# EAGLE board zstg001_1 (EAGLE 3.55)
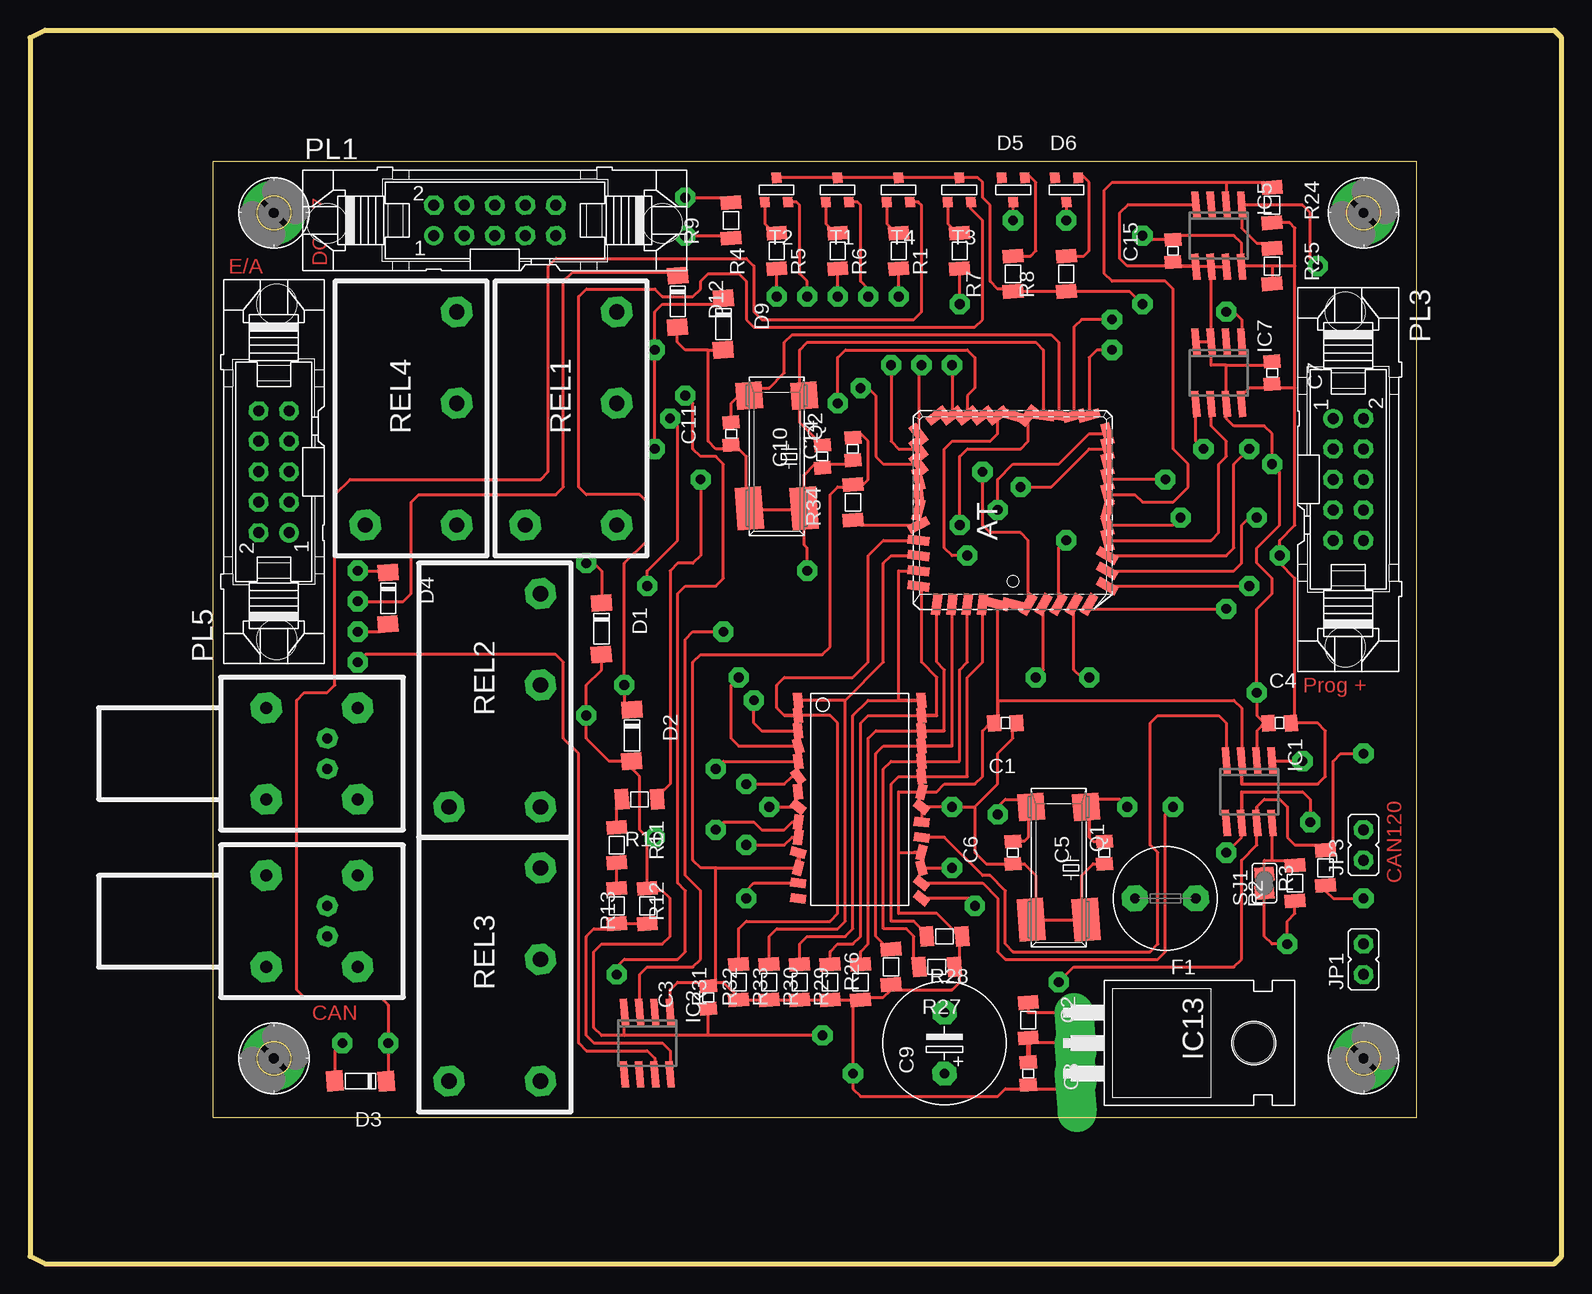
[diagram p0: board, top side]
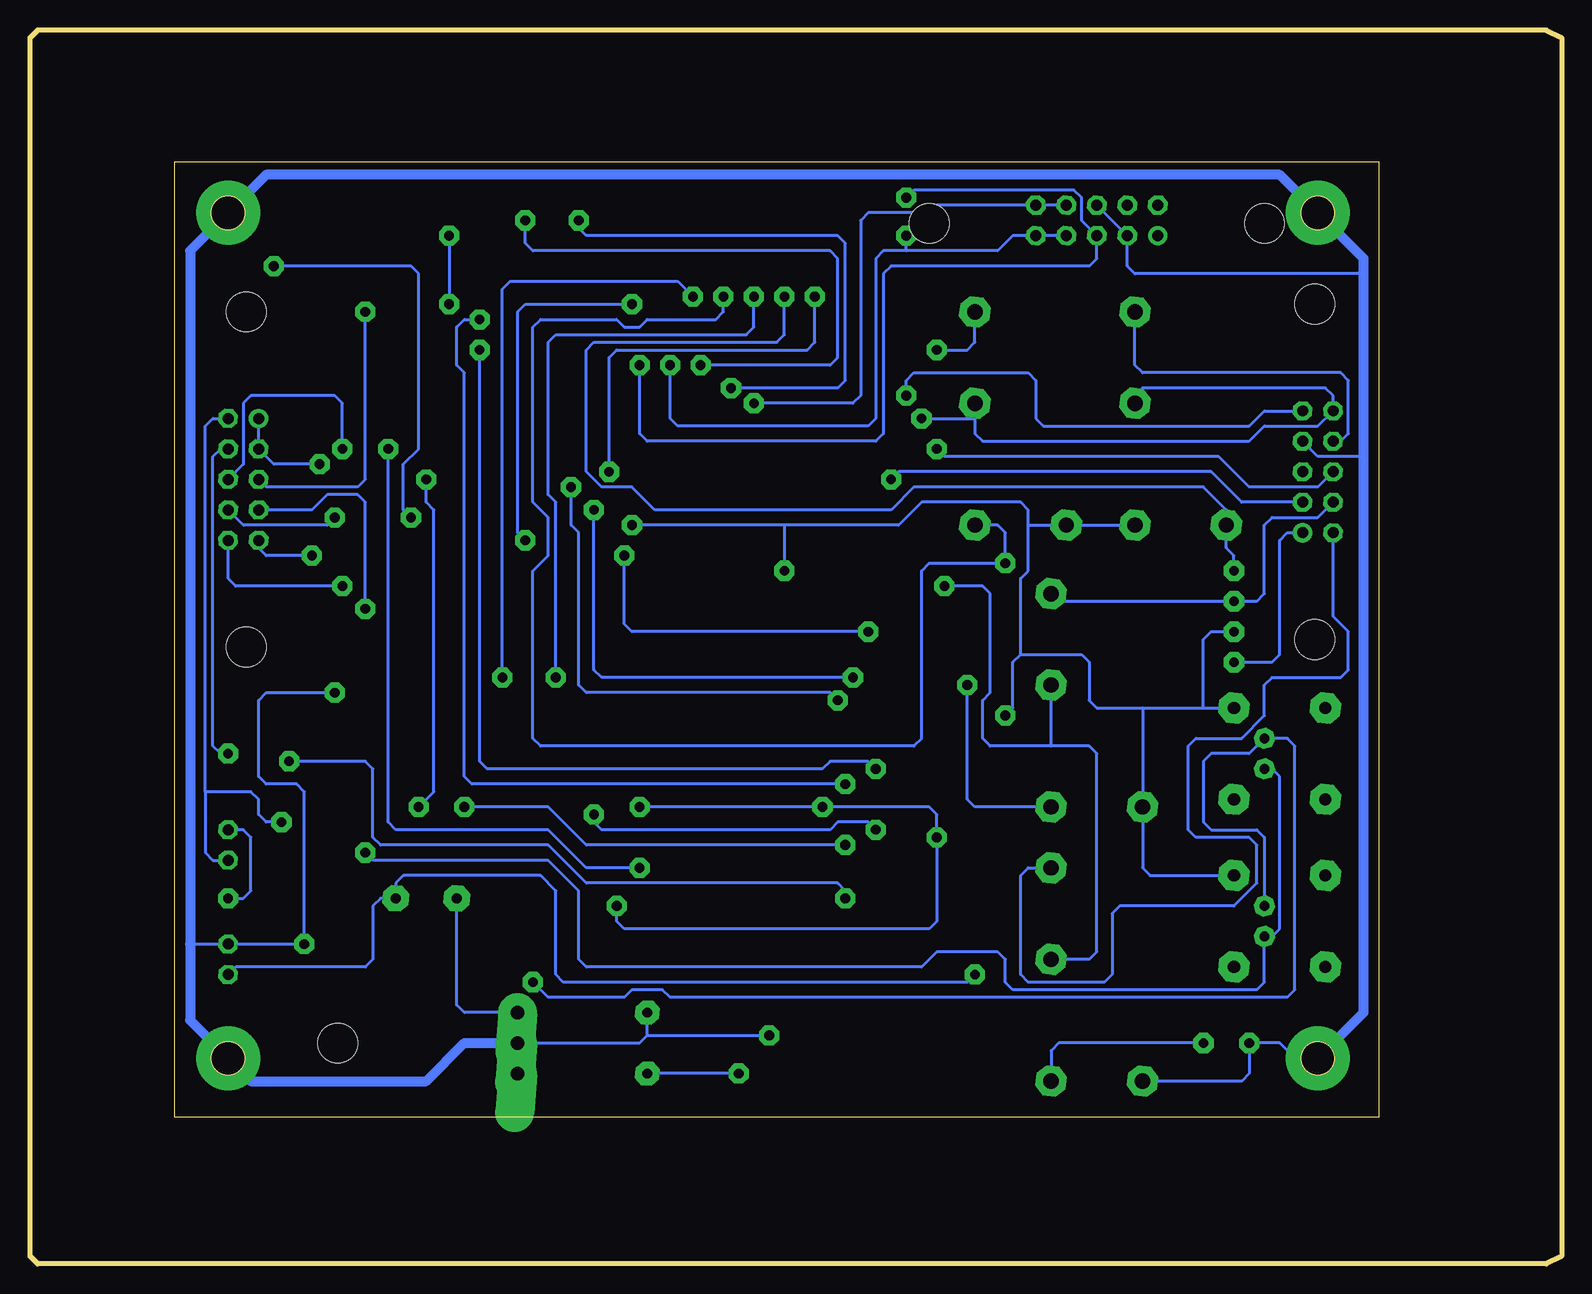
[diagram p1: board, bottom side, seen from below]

Size 127.64 x 102.87 mm. Coordinates in mm from the lower left corner, seen from the top.
Outline: 115.56,12.23 115.56,91.91 15.24,91.91 15.24,12.23 115.56,12.23
Outline: 0,0.63 1.27,0 127,0 127.64,0.63 127.64,102.23 127,102.87 1.27,102.87 0,102.23 0,0.63
Copper layers used: Top, Bottom
vRestrict: area 69.9,50.8 to 94,74.9

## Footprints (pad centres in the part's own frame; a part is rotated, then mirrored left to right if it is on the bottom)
05 = smd 1.092 x 1.397 rotated 4.4:  0.94,0 | smd 1.092 x 1.397 rotated 4.3:  -0.94,0
06 = smd 1.143 x 1.702 rotated 4.4:  1.473,0 | smd 1.143 x 1.702 rotated 4.3:  -1.473,0
-5 = drill 0.813 pad 2.007 octagon:  -2.54,0;  2.54,0
D-80 = smd 1.397 x 1.702 rotated 4.4:  -2.388,0 | smd 1.397 x 1.702 rotated 4.3:  1.905,-0.025
T-23 = smd 0.787 x 0.889 rotated 4.4:  0.991,1.016 | smd 0.787 x 0.889 rotated 4.3:  -0.94,1.016 | smd 0.787 x 0.889 rotated 4.5:  0.025,-1.016
5 = drill 0.813 pad 2.159 octagon:  -2.54,0;  2.54,0
8 = smd 0.6 x 2.2 rotated 4.4:  -0.635,-2.6 | smd 0.6 x 2.2 rotated 4.8:  -0.635,2.6 | smd 0.6 x 2.2 rotated 4.3:  -1.905,-2.6 | smd 0.6 x 2.2 rotated 4.5:  0.635,-2.6 | smd 0.6 x 2.2 rotated 4.6:  1.905,-2.6 | smd 0.6 x 2.2 rotated 4.9:  -1.905,2.6 | smd 0.6 x 2.2 rotated 4.7:  0.635,2.6;  1.905,2.6
CC-44 = smd 0.76 x 1.8 rotated 74.5: 0 -1.27,-7.86; 1 1.27,-7.86; 2 2.54,-7.86; 3 3.81,-7.86; 4 5.08,-7.86; 5 6.35,-7.86; N 2.54,7.86 | smd 1.8 x 0.76 rotated 29.5: 0 -7.86,-1.27; 1 -7.86,-2.54; 2 -7.86,-3.81; 3 -7.86,-5.08; 4 -7.86,-6.35 | smd 1.8 x 0.76 rotated 7: 0 -7.86,2.54; 1 -7.86,3.81; 2 -7.86,5.08; 3 -7.86,6.35 | smd 1.8 x 0.76 rotated 52: 0 7.86,1.27; 1 7.86,2.54; 2 7.86,3.81; 3 7.86,5.08; 4 7.86,6.35 | smd 0.76 x 1.8 rotated 7: 4 -6.35,7.86; 5 -5.08,7.86; 6 -3.81,7.86; 7 -2.54,7.86 | smd 0.76 x 1.8 rotated 52: 5 6.35,7.86; 6 5.08,7.86; 7 3.81,7.86 | smd 0.76 x 1.8 rotated 29.5: 5 -6.35,-7.86; 6 -5.08,-7.86; 7 -3.81,-7.86 | smd 1.8 x 0.76 rotated 74.5: 6 7.86,-6.35; 7 7.86,-5.08 | smd 0.76 x 1.8 rotated 275.7: /PR 1.27,7.86 | smd 1.8 x 0.76 rotated 97.7: L1 7.86,-2.54; L2 7.86,-3.81 | smd 0.76 x 1.8 rotated 28.6: VPP -1.27,7.86 | smd 0.76 x 1.8 rotated 74.7:  -2.54,-7.86 | smd 0.76 x 1.8 rotated 74.4:  0,-7.86;  0,7.86 | smd 1.8 x 0.76 rotated 74.4:  -7.86,0;  7.86,0 | smd 1.8 x 0.76 rotated 75.1:  -7.86,1.27 | smd 1.8 x 0.76 rotated 321.2:  7.86,-1.27
-28L = smd 0.762 x 1.27 rotated 321.2: 1 1.27,-5.207; 2 1.27,5.08; 3 8.89,5.08 | smd 0.762 x 1.27 rotated 75.1: 1 0,5.08; 2 5.08,5.08; 3 6.35,-5.207 | smd 0.762 x 1.27 rotated 74.7: / 6.35,5.08 | smd 0.762 x 1.27 rotated 321.4: / 7.62,5.08 | smd 0.762 x 1.27 rotated 275.7: /AS -5.08,-5.207 | smd 0.762 x 1.27 rotated 97.2: E -2.54,-5.207 | smd 0.762 x 1.27 rotated 344.3: E 5.08,-5.207 | smd 0.762 x 1.27 rotated 97.7: L1 2.54,-5.207; L2 3.81,-5.207 | smd 0.762 x 1.27 rotated 275.9: OUT 0,-5.207 | smd 0.762 x 1.27 rotated 95.7:  -7.62,-5.207;  -6.35,-5.207;  -1.27,5.08;  -2.54,5.08;  -3.81,5.08;  -5.08,5.08;  -6.35,5.08;  -7.62,5.08 | smd 0.762 x 1.27 rotated 73.4:  -3.81,-5.207 | smd 0.762 x 1.27 rotated 52.6:  -1.27,-5.207 | smd 0.762 x 1.27 rotated 187.2:  2.54,5.08;  3.81,5.08 | smd 0.762 x 1.27 rotated 187.4:  8.89,-5.207;  7.62,-5.207
220H = drill 1.118 pad 3.251 offset:  -2.54,-10.16;  0,-10.16;  2.54,-10.16 | hole 3.302: 0,4.826
1 = drill 0.914 pad 1.6 octagon:  0,-1.27;  0,1.27
2,8-P = drill 2.794 pad 5.334 round: 8 0,0
V = drill 0.914 pad 1.6 round:  -5.08,-1.27 | drill 0.914 pad 1.6 octagon:  -5.08,1.27;  -2.54,-1.27;  -2.54,1.27;  0,-1.27;  0,1.27;  2.54,-1.27;  2.54,1.27;  5.08,-1.27;  5.08,1.27 | hole 3.302: 13.97,-0.254; -13.97,-0.254
N_EPL = drill 1.016 pad 2.54 octagon: 1 -3.81,3.81; 2 3.81,3.81; 3 -3.81,-3.81; 4 3.81,-3.81 | drill 0.813 pad 1.676 octagon: H -1.27,1.27; L 1.27,1.27
SMX = smd 3.556 x 2.184 rotated 4.4:  4.318,-2.286 | smd 3.556 x 2.184 rotated 4.5:  4.318,2.286 | smd 2.286 x 2.184 rotated 4.3:  -5.08,-2.286 | smd 2.286 x 2.184 rotated 4.6:  -5.08,2.286
LAIS_R = drill 1.27 pad 2.54 octagon:  -12.7,5.08;  -12.7,-2.54;  -2.54,-2.54;  5.08,-2.54
 = smd 1.168 x 1.6 rotated 4.3:  -0.762,0 | smd 1.168 x 1.6 rotated 4.4:  0.762,0

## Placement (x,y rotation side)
C1  100n  [05]  81.28,45.08 180 top
C2  330n  [06]  83.19,20.32 270 top
C3  100n  [05]  56.52,22.23 90 top
C4  100n  [05]  104.14,45.08 0 top
C5  15pF  [05]  89.53,34.29 90 top
C6  15pF  [05]  81.92,34.29 90 top
C7  100n  [05]  103.5,74.3 270 top
C8  100n  [05]  83.19,15.88 270 top
C9  Elko 470uF  [-5]  76.2,18.41 90 top
C10  30pF +-10pF  [05]  66.04,67.31 90 top
C11  30 pF+-10pF  [05]  58.42,69.22 90 top
C14  100n  [05]  68.58,67.94 90 top
C15  100n  [05]  95.25,84.45 90 top
D1  SMD4148  [D-80]  47.62,52.7 270 top
D2  SMD4148  [D-80]  50.16,43.81 270 top
D3  SMD4148  [D-80]  27.3,15.24 180 top
D4  SMD4148  [D-80]  29.84,55.25 270 top
D5  grn  [T-23]  81.92,89.53 0 top
D6  rot  [T-23]  86.36,89.53 0 top
D9  SMD4148  [D-80]  57.78,78.11 270 top
D12  SMD4148  [D-80]  53.98,80.01 270 top
F1  T200mA  [5]  94.61,30.48 180 top
IC1  PCA82C250  [8]  101.6,39.37 180 top
IC2  DS2450  [8]  51.44,18.41 180 top
IC3  AT89S53  [CC-44]  81.92,62.86 90 top
IC4  SJA1000  [-28L]  69.22,39.37 270 top
IC5  DS1621  [8]  99.06,85.73 180 top
IC7  MAX700  [8]  99.06,74.3 180 top
IC13  78S05  [220H]  97.16,18.41 270 top
JP1  2-polig  [1]  111.12,25.4 0 top
JP3  CAN-Abschluá  [1]  111.12,34.92 0 top
PAD1  BO2,8P  [2,8-P]  20.32,87.63 0 top
PAD2  BO2,8P  [2,8-P]  20.32,17.14 0 top
PAD3  BO2,8P  [2,8-P]  111.12,17.14 0 top
PAD4  BO2,8P  [2,8-P]  111.12,87.63 0 top
PL1  06V  [V]  38.73,87 0 top
PL2  CAN_BUS  [N_EPL]  23.5,28.57 270 top
PL3  10V  [V]  109.86,65.41 270 top
PL4  CAN_BUS  [N_EPL]  23.5,42.55 270 top
PL5  10V  [V]  20.32,66.04 90 top
Q1  16MHZ  [SMX]  85.72,33.02 270 top
Q2  16MHZ  [SMX]  62.23,67.31 270 top
R1  4k7  [06]  77.47,84.45 90 top
R2  47k  [06]  105.41,31.75 90 top
R3  120R  [06]  107.95,33.02 90 top
R4  4k7  [06]  62.23,84.45 90 top
R5  4k7  [06]  67.31,84.45 90 top
R6  4k7  [06]  72.39,84.45 90 top
R7  2k7  [06]  81.92,82.55 90 top
R8  2k7  [06]  86.36,82.55 90 top
R9  10k  [06]  58.42,87 90 top
R10  10k  [06]  50.8,38.73 180 top
R11  10k  [06]  48.9,34.92 270 top
R12  10k  [06]  48.9,29.84 270 top
R13  10k  [06]  51.44,29.84 90 top
R24  1k  [06]  103.5,88.27 270 top
R25  1k  [06]  103.5,83.19 270 top
R26  4k7  [06]  71.75,24.77 90 top
R27  4k7  [06]  75.56,24.77 180 top
R28  4k7  [06]  76.2,27.3 180 top
R29  4k7  [06]  69.22,23.49 90 top
R30  4k7  [06]  66.67,23.49 90 top
R31  4k7  [06]  59.05,23.49 90 top
R32  4k7  [06]  61.59,23.49 90 top
R33  4k7  [06]  64.13,23.49 90 top
R34  4k7  [06]  68.58,63.5 90 top
REL1  REL_RE  [LAIS_R]  46.36,74.3 90 top
REL2  REL_RE  [LAIS_R]  40,50.8 90 top
REL3  REL_RE  [LAIS_R]  40,27.94 90 top
REL4  REL_RE  [LAIS_R]  33.02,74.3 90 top
SJ1  SJ  []  102.87,31.75 90 top
T1  BC818  [T-23]  67.31,89.53 180 top
T2  BC818  [T-23]  62.23,89.53 180 top
T3  BC818  [T-23]  77.47,89.53 180 top
T4  BC818  [T-23]  72.39,89.53 180 top

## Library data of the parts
C1-C8 C10 C11 C14 C15 D1-D6 D9 D12 R1-R13 R24-R34 T1-T4 = smd
C9 = discrete
F1 = fuse
IC1-IC5 IC7 PL2 PL4 REL1-REL4 = andit4at
IC13 = linear
JP1 JP3 = jumps
PAD1-PAD4 = holes
PL1 PL3 PL5 = pinh-v
Q1 Q2 = quartz
SJ1 = jumper

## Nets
+5V: C1. C3. C4. C7. C8. C9. C14. C15. IC1. IC2. IC3. IC4.1 IC4.2 IC4.3 IC4.E IC5. IC7. IC13. PL3. R7. R8. R24. R25. R26. R27. R28. R29. R30. R31. R32. R33. R34. T1. T2. T3. T4.
GND: C1. C2. C3. C4. C5. C6. C7. C8. C9. C10. C11. C14. C15. D1. D2. D3. D4. D9. D12. IC1. IC2. IC3. IC4. IC4.1 IC4.2 IC4.3 IC5. IC7. IC13. JP1. PAD1.8 PAD2.8 PAD3.8 PAD4.8 PL1. PL2.1 PL3. PL4.1 PL5. Q1. Q2. R2. R13. REL1. REL2. REL3. REL4. SJ1.
N$1: IC3.0 IC4. R28.
N$2: IC3.1 IC4. R27.
N$3: IC3.5 IC4. R33.
N$4: IC3.VPP R34.
N$5: IC3.7 IC4. R31.
N$6: IC3.3 R6.
N$7: IC3.2 R1.
N$9: IC1. IC4.
N$10: IC3.1 R5.
N$11: C11. IC3.L2 Q2.
N$13: IC3.0 R4.
N$15: R4. T2.
N$16: IC1. PL2.H PL3. PL4.H R3.
N$17: D3. REL3. T4.
N$18: R5. T1.
N$19: D2. REL2. T3.
N$20: R1. T3.
N$21: R6. T4.
N$22: D1. REL1. T1.
N$23: D6. R8.
N$24: D4. REL4. T2.
N$25: D6. IC3.6
N$26: D5. IC3.7
N$28: IC3.5 PL1. R9.
N$29: PL5. REL1. REL2. REL3. REL4.
N$30: PL5. R10.
N$31: IC3.3 PL1. R9.
N$32: IC3.2 PL1.
N$33: D12. PL5. REL2.
N$34: PL5. REL3.
N$35: D9. PL5. REL1.
N$36: IC1. JP3. PL2.L PL3. PL4.L
N$37: IC3.4 IC4./AS
N$38: IC3.6 PL3.
N$39: IC3.5 PL3.
N$40: IC3.7 PL3.
N$41: IC3. IC7.
N$42: IC3.5 IC4.
N$43: PL5. REL4.
N$44: IC3.1 IC5. R24.
N$45: IC3.0 IC5. R25.
N$46: IC3.6 IC4.E
N$47: IC3.7 IC4.
N$48: IC3.2 IC4./
N$49: IC7. PL3.
N$50: IC4./ IC7.
N$51: C5. IC4.L2 Q1.
N$52: C6. IC4.L1 Q1.
N$53: IC2. R12. R13.
N$54: IC2. IC3.0
N$55: IC1. IC4.
N$56: R10. R11.
N$59: D5. R7.
N$60: C2. F1. IC13.
N$61: F1. JP1. PL5.
N$63: IC1. R2. SJ1.
N$64: R11. R12.
N$65: JP3. R3.
N$69: IC2. PL5.
N$70: C10. IC3.L1 Q2.
N$79: IC3.4 PL3.
N$102: IC3.2 IC4. R26.
N$104: IC3.3 IC4. R29.
N$105: IC3.4 IC4. R30.
N$106: IC3.6 IC4. R32.

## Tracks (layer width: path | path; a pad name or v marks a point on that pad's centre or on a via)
+5V  (via drill 0.81 pad 1.68)
  Top 0.254: 71.96,23.49 R26. 71.75,22.86 | 73.66,34.29 74.3,34.29 72.39,34.29 | 64.13,33.15 IC4.3 | 64.13,33.15 64.13,34.29 | 72.39,34.29 72.39,39.37 IC4.1 75.56,39.37 76.2,40 78.74,40 79.38,40.64 79.38,44.45 80.01,45.08 | 72.39,34.29 72.39,29.21 75.56,29.21 77.47,27.3 R28. 77.47,27.1 77.47,24.77 | 77.47,24.77 R27. | 83.19,14.6 86.36,14.6 86.36,15.24 IC13. | IC4.E 64.01,33.15 64.13,33.02 | 100.97,40 107.31,40 107.95,40.64 107.95,44.45 107.31,45.08 105.41,45.08 | 80.64,46.99 80.64,45.08 80.34,45.08 80.01,45.08 | 80.64,46.99 80.64,55 | 103.5,83.19 100.97,83.19 | 100.97,83.19 100.97,85.09 100.33,85.73 95.25,85.73 95.25,85.39 93.04,85.39 v92.71,85.73 | 105.41,73.03 105.41,83.19 | 103.5,73.03 103.5,73.36 | 105.41,73.03 103.5,73.03 | 103.5,73.03 101.6,73.03 101.03,72.45 101.03,71.75 100.97,71.75 100.97,71.69 | 105.41,73.03 105.41,61.59 104.14,60.33 v104.14,59.05 104.14,58.42 105.41,57.15 105.41,45.08 | 104.78,45.08 105.08,45.08 105.41,45.08 | 103.5,86.79 104.98,86.79 105.41,86.36 105.41,83.19 | 105.41,83.19 103.5,83.19 | 103.5,83.19 103.5,81.71 | 81.92,81.28 R7. | 81.92,81.28 82.12,81.08 R8. 91.64,81.08 v92.71,80.01 | T2. 62.2,90.78 62.23,90.81 62.48,90.55 T1. 67.28,90.78 67.31,90.81 67.56,90.55 T4. 72.37,90.78 72.39,90.81 72.64,90.55 T3. 78.99,90.55 79.38,90.17 79.38,88.9 80.01,88.27 80.01,81.92 80.64,81.28 81.92,81.28 | 68.58,64.97 69.42,64.97 69.85,65.41 | 69.85,65.41 69.85,68.58 69.22,69.22 68.58,69.22 68.58,68.89 | 64.13,33.02 64.13,33.15 | 57.15,33.02 64.13,33.02 | 100.97,40 100.97,41.97 | 53.34,20.95 53.34,21.02 53.34,22.86 53.98,23.49 56.52,23.49 | 56.52,22.86 56.52,23.16 | 57.15,23.49 56.52,22.86
  Top 0.254: 57.15,23.49 57.15,33.02 | 56.52,23.49 57.15,23.49 | 69.85,65.41 69.22,64.77 67.31,64.77 66.67,64.14 66.67,51.44 66.04,50.8 55.88,50.8 55.24,50.17 55.24,33.66 55.88,33.02 57.15,33.02 | 59.05,22.23 59.26,22.02 R32. 61.59,22.23 61.8,22.02 R33. 64.13,22.23 64.34,22.02 R30. 66.67,22.23 66.88,22.02 R29. 69.22,22.23 | 59.05,22.23 R31. | 59.05,22.23 57.78,23.49 56.52,23.49 | 56.52,23.49 56.52,22.86 | 71.75,22.86 71.12,22.23 69.22,22.23 | 83.19,14.6 83.19,14.93 | 83.19,14.6 81.28,14.6 80.64,13.97 69.22,13.97 68.58,14.6 v68.58,15.88 68.58,21.59 69.22,22.23 | 100.97,83.19 100.97,83.12 | 71.75,22.86 76.84,22.86 77.47,23.49 77.47,24.77 | 100.97,40 100.97,46.36 100.33,46.99 80.64,46.99 | 80.01,45.08 80.34,45.42 | 80.64,46.99 80.64,45.72 80.01,45.08
  Bottom 0.254: 108.58,60.33 108.58,59.69 107.95,59.05 v104.14,59.05 | v92.71,85.73 v92.71,80.01 | v68.58,15.88 76.2,15.88
GND  (via drill 0.81 pad 1.68)
  Top 0.254: 87,18.41 83.19,18.41 83.19,19.05 | 99.69,83.12 99.69,83.19 99.64,83.12 98.42,83.12 | C15. 95.25,83.82 95.31,83.76 95.31,83.12 97.09,83.12 97.16,83.19 | 64.52,62.99 64.39,62.86 59.69,62.86 | 59.94,62.99 59.82,62.86 59.69,62.86 | 59.69,62.86 59.69,67.31 59.05,67.94 58.42,67.94 | 98.42,76.89 98.42,76.84 97.22,76.84 97.16,76.89 | 98.42,76.89 98.42,74.93 99.69,74.93 | 99.69,74.93 102.87,74.93 103.5,75.56 C7. | 98.42,76.89 98.42,83.12 | v61.59,38.1 64.01,38.1 | v78.74,29.84 78.74,30.48 74.3,30.48 | 88.01,28.7 83.44,28.7 83.69,28.7 83.82,28.57 83.82,32.38 82.86,33.35 82.25,33.35 81.92,33.02 C6. 79.68,33.35 78.74,34.29 78.74,38.1 | 88.01,28.7 88.14,28.7 88.27,28.57 | 88.01,28.7 87.76,28.7 87.63,28.57 87.63,32.38 88.59,33.35 89.23,33.35 89.53,33.66 C5. | 102.87,45.08 102.23,44.45 102.23,41.97 102.23,41.91 | 78.74,38.1 80.64,40 80.64,42.55 81.92,43.81 81.92,45.08 C1. | C14. 68.28,67 67.94,66.67 66.04,66.67 C10. 66.04,66.04 65.41,66.67 64.52,65.79 64.52,62.99 | 99.69,74.93 99.69,71.69 99.69,70.48 100.33,69.85 102.87,69.85 103.5,69.22 v103.5,66.67 104.14,66.04 104.14,61.59 102.23,59.69 102.23,58.42 103.5,57.15 103.5,55.88 102.23,54.61 v102.23,47.62 102.23,45.72 102.87,45.08 | 97.16,88.33 91.5,88.33 90.81,87.63 90.81,83.82 91.44,83.19 97.16,83.19 | 97.16,83.19 IC5. 98.36,83.12 98.42,83.19 98.42,83.12 | 64.52,62.99 64.52,59.94 64.77,59.69 v64.77,57.78 | 58.42,67.94 C11. | 74.3,36.83 IC4.2 v76.84,38.1 78.74,38.1 | 56.52,19.05 49.53,19.05 | v66.04,19.05 56.52,19.05 | 56.52,21.59 C3. 56.52,19.05 | 49.53,20.95 49.53,21.02 | 102.87,45.08 C4. | v27.3,52.7 29.21,52.7 29.84,53.34 D4.
  Top 0.254: v26.04,18.41 25.4,17.78 D3. 25.4,15.24 | 51.44,35.56 50.8,36.2 50.8,40.64 50.14,41.3 D2. 48.26,41.91 46.36,43.81 v46.36,45.72 46.36,48.26 47.62,49.53 47.62,50.8 D1. | 51.44,35.56 v52.07,35.56 | 51.44,35.56 51.44,31.32 51.44,31.11 52.7,31.11 53.34,30.48 53.34,27.3 52.7,26.67 47.62,26.67 46.99,26.04 46.99,19.68 47.62,19.05 49.53,19.05 | 49.53,19.05 49.53,20.95 | 49.53,20.95 49.53,21.59 | D12. 53.95,76.86 54.61,76.2 56.52,76.2 | 57.78,76.2 D9. 56.52,76.2 | 58.42,67.94 57.15,67.94 56.52,68.58 56.52,76.2 | 83.19,70.72 83.19,68.58 82.55,67.94 78.1,67.94 77.47,67.31 v77.47,61.59 | R2. 105.41,29.21 104.78,28.57 v104.78,26.67 103.5,26.67 102.87,27.3 102.87,30.99
  Top 0.406: C8. 83.19,18.41 83.19,18.85
  Bottom 0.254: 76.2,19.05 C9. | 76.2,19.05 v66.04,19.05 | 87,18.41 76.84,18.41 76.2,19.05 | 108.58,70.48 108.58,67.94 107.31,66.67 v103.5,66.67 | 38.73,88.27 36.2,85.73 36.2,83.19 35.56,82.55 16.51,82.55 | v102.23,47.62 107.95,47.62 108.58,46.99 108.58,40.64 107.95,40 105.41,40 104.78,39.37 v104.78,26.67 JP1. 114.3,26.67 | v76.84,38.1 v61.59,38.1 52.7,38.1 52.07,37.47 v52.07,35.56 52.07,28.57 52.7,27.94 78.1,27.94 78.74,28.57 v78.74,29.84 | 21.59,68.58 20.32,67.31 16.51,67.31 | 29.84,46.36 PL4.1 | 29.84,46.36 29.84,52.07 29.21,52.7 v27.3,52.7 | PAD2.8 22.23,17.14 23.5,18.41 v26.04,18.41 26.04,15.88 26.67,15.24 34.92,15.24 | 34.92,46.36 38.73,46.36 39.37,46.99 39.37,50.17 40,50.8 45.09,50.8 | PL2.1 34.29,32.38 34.92,33.02 34.92,38.1 34.92,46.36 | 45.09,50.8 45.09,57.15 44.45,57.78 44.45,61.59 | 44.45,61.59 41.27,61.59 35.56,61.59 | 45.09,50.8 45.72,50.17 45.72,46.36 v46.36,45.72 | 34.92,46.36 29.84,46.36 | 64.77,61.59 v77.47,61.59 | 64.77,61.59 55.24,61.59 53.34,63.5 45.09,63.5 44.45,62.86 44.45,61.59 | 64.77,61.59 v64.77,57.78
  Bottom 0.813: PAD2.8 16.51,20.95 16.51,67.31 16.51,82.55 16.51,83.82 PAD1.8 23.5,90.81 107.95,90.81 PAD4.8 114.3,84.45 114.3,26.67 114.3,20.32 PAD3.8 109.22,15.24 94.61,15.24 91.44,18.41 87,18.41
N$1
  Top 0.254: 79.38,55 79.38,50.17 78.1,48.89 78.1,40.64 74.3,40.64 72.39,40.64 71.75,40 71.75,28.57 73.66,28.57 74.93,27.3 74.73,27.3
N$2
  Top 0.254: 78.1,55 78.1,50.17 77.47,49.53 77.47,41.91 74.3,41.91 71.75,41.91 71.12,41.27 71.12,27.94 73.03,27.94 73.66,27.3 73.66,25.4 74.3,24.77 74.09,24.77
N$3
  Top 0.254: 74.06,57.78 72.39,57.78 72.39,46.99 IC4. 69.85,46.99 68.58,45.72 68.58,27.94 67.94,27.3 64.77,27.3 64.13,26.67 64.13,24.97
N$4
  Top 0.254: R34. 68.58,62.23 69.22,61.59 IC3.VPP
N$5
  Top 0.254: 74.06,60.33 71.12,60.33 69.85,59.05 69.85,50.17 68.58,48.89 62.87,48.89 62.23,48.26 62.23,46.36 62.87,45.72 | 64.13,45.72 64.01,45.72 62.87,45.72 | 62.87,45.72 66.67,45.72 67.31,45.08 67.31,29.21 66.67,28.57 59.69,28.57 59.05,27.94 59.05,24.97 59.05,24.77
N$6  (via drill 0.81 pad 1.68)
  Top 0.254: v88.27,48.89 87.63,48.89 87,49.53 87,55 | v72.39,80.64 R6.
  Bottom 0.254: v88.27,48.89 88.27,81.28 87.63,81.92 73.66,81.92 v72.39,80.64
N$7  (via drill 0.81 pad 1.68)
  Top 0.254: 85.72,55 85.72,59.69 v86.36,60.33 | v77.47,80.01 R1.
  Bottom 0.254: v86.36,60.33 87,60.96 87,79.38 86.36,80.01 v77.47,80.01
N$9  (via drill 0.81 pad 1.68)
  Top 0.254: 64.01,31.75 60.33,31.75 59.69,31.11 v59.69,30.48 | 103.5,41.97 103.5,41.91 v106.05,41.91
  Bottom 0.254: v59.69,30.48 59.69,31.11 60.33,31.75 81.28,31.75 84.45,34.92 98.42,34.92 99.06,35.56 99.06,41.27 99.69,41.91 v106.05,41.91
N$10  (via drill 0.81 pad 1.68)
  Top 0.254: v83.82,48.89 84.45,49.53 84.45,55 | v67.31,80.64 R5.
  Bottom 0.254: v83.82,48.89 83.82,63.5 84.45,64.14 84.45,76.84 83.82,77.47 67.94,77.47 67.31,78.11 v67.31,80.64
N$11
  Top 0.254: 58.42,69.85 58.42,70.16 58.42,71.75 59.05,72.39 59.94,72.39 60.33,72.39 59.69,73.03 61.59,73.03 62.87,74.3 62.87,76.84 63.5,77.47 85.09,77.47 85.72,76.84 IC3.L2
N$13  (via drill 0.81 pad 1.68)
  Top 0.254: 83.19,55 83.19,60.33 82.55,60.96 80.01,60.96 79.38,61.59 v79.38,66.04 | v62.23,80.64 R4.
  Bottom 0.254: v79.38,66.04 79.38,75.56 78.74,76.2 62.87,76.2 62.23,76.84 v62.23,80.64
N$15
  Top 0.254: 61.24,88.52 61.24,86.72 62.23,85.73 62.23,85.93
N$16  (via drill 0.81 pad 1.68)
  Top 0.254: v111.12,42.55 109.22,42.55 108.58,41.91 108.58,34.92 107.95,34.92 | 107.95,34.92 105.41,34.92 104.78,35.56 104.78,38.1 104.14,38.73 102.87,38.73 102.23,38.1 | 102.23,38.1 102.23,36.77 | 107.95,34.29 107.95,34.49 107.95,34.92 | 102.23,38.1 102.23,34.92 100.97,33.66 100.97,25.4 100.33,24.77 87,24.77 v85.72,23.49
  Bottom 0.254: 111.12,67.94 111.76,67.94 112.39,67.31 112.39,43.18 111.76,42.55 v111.12,42.55 | PL2.H 24.77,35.56 25.4,36.2 29.21,36.2 29.84,36.83 29.84,41.91 29.21,42.55 26.04,42.55 PL4.H 22.86,43.81 22.23,43.18 22.23,22.86 22.86,22.23 74.3,22.23 74.93,22.86 77.47,22.86 78.1,22.23 84.45,22.23 v85.72,23.49
N$17  (via drill 0.81 pad 1.68)
  Top 0.254: 73.33,88.52 74.04,88.52 74.3,88.27 74.3,79.38 73.66,78.74 60.96,78.74 60.33,79.38 60.33,83.19 59.69,83.82 43.81,83.82 43.18,83.19 43.18,66.04 42.55,65.41 26.67,65.41 25.4,64.14 25.4,48.26 24.77,47.62 22.86,47.62 22.23,46.99 22.23,22.86 22.86,22.23 29.21,22.23 29.84,21.59 v29.84,18.41 29.84,15.24 29.69,15.24
  Bottom 0.254: v29.84,18.41 41.91,18.41 42.55,17.78 42.55,15.24
N$18
  Top 0.254: 66.32,88.52 66.32,86.72 67.31,85.73 67.31,85.93
N$19  (via drill 0.81 pad 1.68)
  Top 0.254: 78.41,88.52 78.41,87.96 79.38,87 79.38,78.74 78.74,78.11 60.33,78.11 59.69,78.74 59.69,81.92 59.05,82.55 56.52,82.55 55.88,81.92 55.88,81.28 55.24,80.64 52.7,80.64 52.07,81.28 46.36,81.28 45.72,80.64 45.72,64.77 46.36,64.14 50.8,64.14 51.44,63.5 51.44,60.33 49.53,58.42 v49.53,48.26 49.53,46.36 50.16,46.36 50.16,46.2
  Bottom 0.254: 42.55,38.1 48.9,38.1 49.53,38.73 v49.53,48.26
N$20
  Top 0.254: 76.48,88.52 76.48,86.72 77.47,85.73 77.47,85.93
N$21
  Top 0.254: 71.4,88.52 71.4,86.72 72.39,85.73 72.39,85.93
N$22  (via drill 0.81 pad 1.68)
  Top 0.254: 68.25,88.52 68.96,88.52 69.22,88.27 69.22,81.92 69.85,81.28 v69.85,80.64 | v46.36,58.42 46.99,58.42 47.62,57.78 47.62,55.09
  Bottom 0.254: v69.85,80.64 69.85,79.38 70.48,78.74 76.2,78.74 76.84,78.11 78.1,78.11 78.74,78.74 85.09,78.74 85.72,78.11 85.72,63.5 84.45,62.23 84.45,59.05 85.72,57.78 85.72,43.81 85.09,43.18 53.98,43.18 53.34,43.81 53.34,57.78 52.7,58.42 v46.36,58.42 46.36,60.96 46.99,61.59 48.9,61.59
N$23
  Top 0.254: 86.36,84.02 87.83,84.02 88.27,84.45 88.27,90.17 87.63,90.81 87.38,90.55 87.35,90.55
N$24  (via drill 0.81 pad 1.68)
  Top 0.254: 63.17,88.52 63.88,88.52 64.13,88.27 64.13,82.55 64.77,81.92 v64.77,80.64 | 29.84,57.63 29.84,57.78 v27.3,57.78
  Bottom 0.254: v64.77,80.64 64.77,77.47 65.41,76.84 80.64,76.84 81.28,76.2 81.28,66.04 80.01,64.77 77.47,64.77 75.56,62.86 55.88,62.86 53.98,64.77 29.84,64.77 27.94,62.86 27.94,61.59 27.94,59.69 27.3,59.05 v27.3,57.78
N$25  (via drill 0.81 pad 1.68)
  Top 0.254: 74.06,67.94 72.39,67.94 71.75,68.58 v71.75,74.93 | D6. 86.39,87.02 v86.36,87
  Bottom 0.254: v71.75,74.93 60.96,74.93 60.33,75.56 60.33,83.82 60.96,84.45 85.72,84.45 86.36,85.09 v86.36,87
N$26  (via drill 0.81 pad 1.68)
  Top 0.254: 74.06,66.67 71.12,66.67 70.48,67.31 70.48,72.39 69.85,73.03 v69.22,73.03 | D5. 81.94,87.02 v81.92,87
  Bottom 0.254: v69.22,73.03 60.33,73.03 59.69,73.66 59.69,85.09 60.33,85.73 81.28,85.73 81.92,86.36 v81.92,87
N$28  (via drill 0.81 pad 1.68)
  Top 0.254: 74.06,69.22 74.06,74.69 v74.3,74.93 | R9. 58.42,85.73 v54.61,85.73
  Bottom 0.254: 41.27,85.73 45.72,85.73 46.99,84.45 54.61,84.45 | 54.61,84.45 v54.61,85.73 | v74.3,74.93 74.3,70.48 73.66,69.85 57.78,69.85 57.15,70.48 57.15,83.82 56.52,84.45 54.61,84.45
N$29  (via drill 0.81 pad 1.68)
  Top 0.254: v53.34,70.48 53.98,69.85 53.98,60.33 51.44,57.78 v51.44,56.52
  Bottom 0.254: 48.9,70.48 48.9,69.22 48.26,68.58 26.04,68.58 24.77,69.85 20.32,69.85 PL5. 19.05,72.39 19.68,73.03 34.92,73.03 35.56,72.39 35.56,71.75 | v53.34,70.48 48.9,70.48 | 48.9,70.48 48.9,71.75 | 42.55,43.18 47.62,43.18 48.26,43.81 48.26,46.99 47.62,47.62 47.62,55.88 48.26,56.52 v51.44,56.52 | 42.55,43.18 42.55,48.26 | 42.55,43.18 39.37,43.18 38.73,42.55 38.73,26.04 39.37,25.4 42.55,25.4
N$30  (via drill 0.81 pad 1.68)
  Top 0.254: v55.88,65.41 55.88,59.05 55.24,58.42 53.98,58.42 53.34,57.78 53.34,40 52.07,38.73 R10.
  Bottom 0.254: 21.59,63.5 26.67,63.5 29.21,66.04 55.24,66.04 v55.88,65.41
N$31  (via drill 0.81 pad 1.68)
  Top 0.254: v76.84,74.93 76.84,70.72 | 58.42,88.47 58.42,88.9 v54.61,88.9
  Bottom 0.254: v54.61,88.9 53.98,89.53 40.64,89.53 40,88.9 40,87 38.73,85.73 38.73,83.82 39.37,83.19 55.88,83.19 56.52,82.55 56.52,69.22 57.15,68.58 76.2,68.58 76.84,69.22 v76.84,74.93
N$32  (via drill 0.81 pad 1.68)
  Top 0.254: 78.1,70.72 78.1,72.39 78.74,73.03 78.74,75.56 78.1,76.2 67.94,76.2 67.31,75.56 v67.31,71.75
  Bottom 0.254: 41.27,88.27 52.07,88.27 52.7,87.63 57.78,87.63 58.42,87 58.42,72.39 59.05,71.75 v67.31,71.75
N$33  (via drill 0.81 pad 1.68)
  Top 0.254: v27.3,55.25 31.12,55.25 31.75,55.88 31.75,63.5 32.39,64.14 43.81,64.14 44.45,64.77 44.45,81.92 45.24,82.7 53.19,82.7 53.34,82.55 53.98,82.55 | 53.98,82.55 53.82,82.7 | 53.98,81.92 53.98,82.4 53.98,82.55
  Bottom 0.254: 19.05,63.5 20.32,62.23 24.13,62.23 24.77,61.59 24.77,55.88 25.4,55.25 v27.3,55.25 41.91,55.25 REL2.
N$34
  Bottom 0.254: 19.05,60.96 19.05,53.97 17.78,52.7 17.78,49.53 18.41,48.89 24.13,48.89 24.77,48.26 24.77,45.72 26.67,43.81 30.48,43.81 31.12,43.18 31.12,36.2 30.48,35.56 26.04,35.56 25.4,34.92 25.4,31.75 27.3,29.84 36.83,29.84 37.47,29.21 37.47,24.13 38.1,23.49 44.45,23.49 45.09,24.13 45.09,32.38 44.45,33.02 REL3.
N$35  (via drill 0.81 pad 1.68)
  Top 0.254: v52.07,67.94 v52.07,76.2 52.07,79.38 52.7,80.01 57.15,80.01 | 57.15,80.01 57.78,80.64 | 57.78,80.64 57.15,80.64 | 57.78,80.64 57.78,80.49 57.78,80.01 57.15,80.01
  Bottom 0.254: 19.05,66.04 20.32,64.77 26.04,64.77 28.57,67.31 51.44,67.31 v52.07,67.94 | REL1. 48.9,76.84 49.53,76.2 v52.07,76.2
N$36  (via drill 0.81 pad 1.68)
  Top 0.254: 100.97,39.37 100.97,36.77 | 100.97,39.37 106.05,39.37 106.68,38.73 v106.68,36.83 | 100.97,39.37 100.97,35.56 v99.69,34.29
  Bottom 0.254: 106.68,36.2 v106.68,36.83 107.95,36.83 108.58,37.47 108.58,38.73 109.22,39.37 113.03,39.37 | 111.12,70.48 112.39,70.48 113.03,69.85 113.03,39.37 | 111.12,33.66 112.39,33.66 113.03,34.29 113.03,39.37 | PL4.L 24.13,41.27 23.5,40.64 23.5,27.94 24.13,27.3 PL2.L 24.77,23.49 25.4,22.86 45.72,22.86 46.36,23.49 46.36,25.4 46.99,26.04 52.07,26.04 53.34,24.77 81.28,24.77 81.92,25.4 81.92,31.11 84.45,33.66 99.06,33.66 v99.69,34.29
N$37  (via drill 0.81 pad 1.68)
  Top 0.254: 89.78,67.94 88.27,67.94 85.09,64.77 v82.55,64.77 | v60.33,46.99 60.33,45.08 60.96,44.45 IC4./AS
  Bottom 0.254: v82.55,64.77 82.55,61.59 81.92,60.96 81.92,48.26 81.28,47.62 60.96,47.62 v60.33,46.99
N$38  (via drill 0.81 pad 1.68)
  Top 0.254: 89.78,57.78 100.33,57.78 100.97,58.42 100.97,61.59 101.6,62.23 v102.23,62.23
  Bottom 0.254: 111.12,62.86 109.86,61.59 102.87,61.59 v102.23,62.23
N$39  (via drill 0.81 pad 1.68)
  Top 0.254: IC3.5 v101.6,56.52
  Bottom 0.254: PL3. 111.12,57.15 110.49,56.52 v101.6,56.52
N$40  (via drill 0.81 pad 1.68)
  Top 0.254: 89.78,59.05 99.69,59.05 100.33,59.69 100.33,66.67 v101.6,67.94
  Bottom 0.254: 111.12,65.41 109.86,66.67 109.86,71.75 109.22,72.39 102.23,72.39 101.6,71.75 v101.6,67.94
N$41
  Top 0.254: 89.78,60.33 98.42,60.33 99.06,60.96 99.06,66.67 99.69,67.31 99.69,68.58 98.42,69.85 98.42,71.69
N$42  (via drill 0.81 pad 1.68)
  Top 0.254: 89.78,69.22 88.27,69.22 85.72,66.67 81.92,66.67 80.64,65.41 v80.64,62.86 | v59.05,48.89 58.42,48.26 58.42,43.81 59.05,43.18 64.01,43.18
  Bottom 0.254: v80.64,62.86 80.64,49.53 80.01,48.89 v59.05,48.89
N$43
  Bottom 0.254: 19.05,68.58 18.41,68.58 17.78,69.22 17.78,73.66 18.41,74.3 34.92,74.3 35.56,74.93 REL4.
N$44
  Top 0.254: 99.69,88.27 99.69,88.33 99.69,90.17 | 89.78,64.14 92.08,64.14 92.71,63.5 95.25,63.5 96.52,64.77 96.52,66.67 95.25,67.94 95.25,81.28 94.61,81.92 90.17,81.92 89.53,82.55 89.53,89.53 90.17,90.17 99.69,90.17 | R24. 103.5,89.53 102.87,90.17 99.69,90.17
N$45  (via drill 0.81 pad 1.68)
  Top 0.254: 89.78,61.59 95.25,61.59 v95.89,62.23 | 100.97,88.27 100.97,88.33 | 102.23,85.09 102.87,85.09 103.5,84.45 | 103.5,84.45 R25. | 103.5,84.45 103.5,85.09 102.23,85.09 | 102.23,85.09 100.97,86.36 100.97,88.27 | 100.97,88.27 106.05,88.27 106.68,87.63 106.68,83.82 v107.31,83.19
  Bottom 0.254: v107.31,83.19 95.89,83.19 95.25,82.55 95.25,67.94 96.52,66.67 96.52,62.86 v95.89,62.23
N$46  (via drill 0.81 pad 1.68)
  Top 0.254: 88.27,70.72 88.27,75.56 88.9,76.2 v90.17,76.2 | v57.15,41.27 57.78,41.91 64.01,41.91
  Bottom 0.254: v90.17,76.2 90.17,41.91 89.53,41.27 61.59,41.27 60.96,41.91 57.78,41.91 v57.15,41.27
N$47  (via drill 0.81 pad 1.68)
  Top 0.254: IC3.7 87,78.11 87.63,78.74 v90.17,78.74 | 64.01,40.64 63.5,40.64 62.87,40 v59.69,40
  Bottom 0.254: v90.17,78.74 91.44,78.74 92.08,78.11 92.08,74.93 91.44,74.3 91.44,40.64 90.81,40 v59.69,40
N$48  (via drill 0.81 pad 1.68)
  Top 0.254: v94.61,65.41 89.78,65.41 | IC4./ 79.38,31.75 80.64,30.48 80.64,26.04 81.28,25.4 93.98,25.4 94.61,26.04 94.61,37.47 v95.25,38.1
  Bottom 0.254: v94.61,65.41 94.61,63.5 93.98,62.86 93.98,39.37 v95.25,38.1
N$49  (via drill 0.81 pad 1.68)
  Top 0.254: v99.69,79.38 100.33,79.38 100.97,78.74 100.97,76.89
  Bottom 0.254: 108.58,65.41 107.95,64.77 100.33,64.77 99.69,65.41 v99.69,79.38
N$50  (via drill 0.81 pad 1.68)
  Top 0.254: v97.79,67.94 97.16,68.58 IC7. | 74.3,33.02 v76.84,33.02 74.3,33.02
  Bottom 0.254: v97.79,67.94 97.79,36.83 97.16,36.2 84.45,36.2 81.28,33.02 v76.84,33.02
N$51  (via drill 0.81 pad 1.68)
  Top 0.254: IC4.L2 63.5,35.56 62.87,34.92 v59.69,34.92 | 88.27,35.56 88.27,37.47 87.63,38.1 Q1. | 89.53,35.23 88.59,35.23 88.27,35.56 | 88.27,35.56 88.27,38.73 90.81,38.73 v91.44,38.1
  Bottom 0.254: v59.69,34.92 81.28,34.92 84.45,38.1 v91.44,38.1
N$52  (via drill 0.81 pad 1.68)
  Top 0.254: IC4.L1 63.5,36.83 62.87,36.2 60.96,36.2 60.33,36.83 57.78,36.83 v57.15,36.2 | 83.19,38.1 83.19,38.73 81.28,38.73 80.64,38.1 v80.64,37.47 | 83.19,38.1 83.19,35.56 82.86,35.23 82.22,35.23 81.92,34.92 81.92,35.23 | 83.19,38.1 83.44,38.1
  Bottom 0.254: v57.15,36.2 57.78,36.83 60.33,36.83 60.96,36.2 80.01,36.2 80.64,36.83 v80.64,37.47
N$53
  Top 0.254: 53.34,15.81 53.34,17.78 52.7,18.41 46.99,18.41 46.36,19.05 46.36,27.3 46.99,27.94 48.26,27.94 48.9,28.57 | R13. 49.1,28.37 48.9,28.57 | 48.9,28.57 48.9,28.37
N$54  (via drill 0.81 pad 1.68)
  Top 0.254: IC3.0 80.64,69.22 80.01,68.58 76.84,68.58 76.2,67.94 76.2,59.69 76.84,59.05 v78.1,59.05 | v57.78,52.7 55.24,52.7 54.61,52.07 54.61,32.38 55.88,31.11 55.88,25.4 55.24,24.77 51.44,24.77 50.8,24.13 50.8,21.02 50.8,20.95
  Bottom 0.254: v57.78,52.7 77.47,52.7 78.1,53.34 v78.1,59.05
N$55
  Top 0.254: 74.3,35.56 76.2,35.56 79.38,32.38 80.01,32.38 81.28,31.11 81.28,26.67 81.92,26.04 93.34,26.04 93.98,26.67 93.98,34.29 93.34,34.92 93.34,45.08 93.98,45.72 99.06,45.72 99.69,45.08 99.69,41.97
N$56
  Top 0.254: 49.33,38.73 49.33,38.53 48.9,38.1 R11. 48.9,36.2
N$59
  Top 0.254: 81.92,84.02 83.39,84.02 83.82,84.45 83.82,90.17 83.19,90.81 82.93,90.55 82.91,90.55
N$60
  Top 0.254: C2. 83.19,20.95 87,20.95
  Bottom 0.254: F1. 92.08,21.59 91.44,20.95 87,20.95
N$61  (via drill 0.81 pad 1.68)
  Top 0.254: v54.61,72.39 55.24,71.75 55.24,67.94 55.88,67.31 57.15,67.31 57.78,66.67 57.78,57.15 57.15,56.52 54.61,56.52 53.98,55.88 53.98,31.75 54.61,31.11 54.61,26.04 53.98,25.4 49.53,25.4 48.9,24.77 v48.9,24.13
  Bottom 0.254: 111.12,24.13 110.49,24.77 99.69,24.77 99.06,25.4 99.06,29.84 98.42,30.48 97.16,30.48 97.16,31.75 96.52,32.38 85.09,32.38 83.82,31.11 83.82,24.13 83.19,23.49 49.53,23.49 v48.9,24.13 | 21.59,71.12 24.77,71.12 26.04,69.85 43.18,69.85 43.81,70.48 43.81,73.66 44.45,74.3 53.98,74.3 54.61,73.66 v54.61,72.39
N$63
  Top 0.254: 105.41,33.22 105.41,33.02 104.78,33.66 103.5,33.66 | 103.5,33.66 103.5,36.77 | 103.5,33.66 102.87,33.66 SJ1. 102.87,32.38
N$64
  Top 0.254: 48.9,31.11 R12. 48.9,33.45
N$65  (via drill 0.81 pad 1.68)
  Top 0.254: R3. 107.95,31.11 108.58,30.48 v111.12,30.48
  Bottom 0.254: JP3. 109.86,36.2 109.22,35.56 109.22,31.11 109.86,30.48 v111.12,30.48
N$69  (via drill 0.81 pad 1.68)
  Top 0.254: v27.3,50.17 27.94,50.8 43.81,50.8 44.45,50.17 44.45,43.81 45.72,42.55 45.72,18.41 46.36,17.78 51.44,17.78 52.07,17.14 52.07,15.81
  Bottom 0.254: 21.59,60.96 22.86,60.96 23.5,60.33 23.5,50.8 24.13,50.17 v27.3,50.17
N$70
  Top 0.254: 64.13,72.39 Q2. 64.13,72.77 | 66.04,68.25 64.13,70.16 64.13,71.75 | 64.13,71.75 64.13,72.39 | IC3.L1 84.45,76.2 83.82,76.84 64.77,76.84 64.13,76.2 64.13,72.39 | 64.13,72.39 64.77,72.39 64.77,71.75 64.13,71.75
N$79  (via drill 0.81 pad 1.68)
  Top 0.254: 88.27,55 88.27,54.61 v99.69,54.61
  Bottom 0.254: 108.58,62.86 104.14,62.86 102.87,64.14 100.33,64.14 99.69,63.5 v99.69,54.61
N$102
  Top 0.254: 76.84,55.25 IC3.2 76.84,43.18 | 76.84,43.18 74.3,43.18 | 76.84,43.18 71.12,43.18 70.48,42.55 70.48,27.3 71.55,26.24 71.75,26.24
N$104
  Top 0.254: 76.2,44.45 76.2,49.53 75.56,50.17 IC3.3 | 76.2,44.45 74.3,44.45 | 76.2,44.45 70.48,44.45 69.85,43.81 69.85,26.67 69.22,26.04 69.22,24.97
N$105
  Top 0.254: IC3.4 74.3,56.52 74.3,50.17 75.56,48.89 75.56,45.72 | 75.56,45.72 74.3,45.72 | 75.56,45.72 69.85,45.72 69.22,45.08 69.22,27.3 68.58,26.67 67.31,26.67 66.67,26.04 66.67,24.97
N$106
  Top 0.254: IC3.6 71.75,59.05 71.12,58.42 71.12,50.17 67.94,46.99 | 67.94,46.99 64.01,46.99 | 67.94,46.99 67.94,28.57 67.31,27.94 62.23,27.94 61.59,27.3 61.59,24.97 61.59,24.77

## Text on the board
Top: E/A | DCF77 | Prog + | CAN120 | CAN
